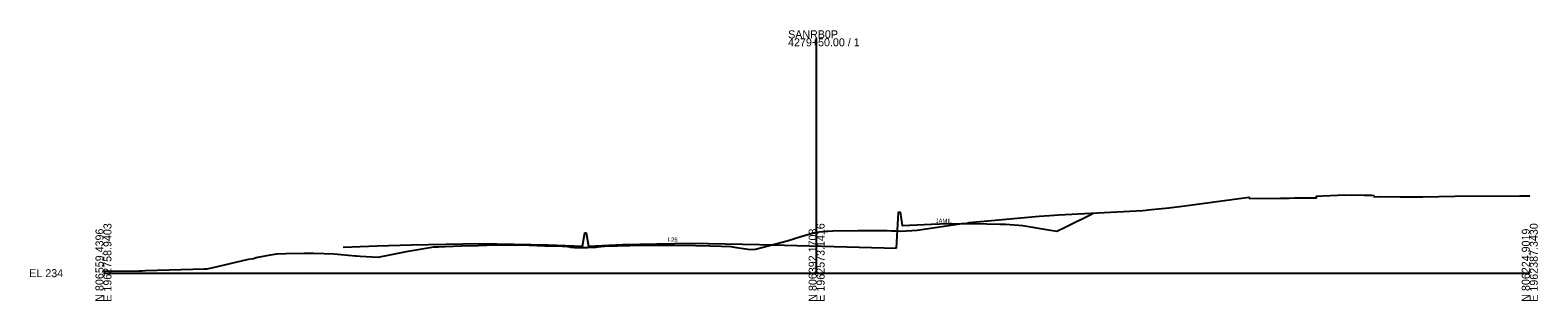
# Model space of a CAD drawing. Extents: x 1995641 to 1997170, y 790368 to 809963.
# Drawn here: x 1995641 to 1996170, y 790368 to 790463 of the extents above; entities that cross this region are included whole.
import ezdxf

# ---------------------------------------------------------------- set-up
doc = ezdxf.new("R2010")
doc.units = 0
for name, color, linetype in [('Default', 7, 'Continuous'), ('RD_GPK_XS_Cell', 7, 'Continuous'), ('RD_Sketch1', 7, 'Continuous'), ('RD_XS_ExGround', 7, 'Continuous'), ('RD_XS_Pave', 7, 'Continuous')]:
    doc.layers.add(name, color=color, linetype=linetype)

msp = doc.modelspace()

# ---------------------------------------------------------------- linework, layer by layer
at = {"layer": 'RD_GPK_XS_Cell'}
for p, q in [((1995917.06, 790378.11), (1995917.06, 790460.38)), ((1995667.06, 790378.11), (1995917.06, 790378.11)), ((1995917.06, 790378.11), (1996167.06, 790378.11))]:
    msp.add_line(p, q, dxfattribs=at)
at = {"layer": 'RD_XS_ExGround'}
msp.add_lwpolyline([(1995667.06, 790378.86), (1995679.41, 790378.96), (1995680.65, 790378.97), (1995681.75, 790378.99), (1995702.43, 790379.57), (1995703.46, 790379.59), (1995707.02, 790380.49), (1995717.86, 790383.07), (1995719.62, 790383.3), (1995720.62, 790383.6), (1995725.64, 790384.55), (1995726.98, 790384.72), (1995727.7, 790384.85), (1995730.97, 790384.97), (1995737.37, 790385.15), (1995740.79, 790385.08), (1995747.92, 790384.91), (1995755.32, 790384.22), (1995755.75, 790384.18), (1995757.05, 790384.1), (1995763.37, 790383.74), (1995773.85, 790385.79), (1995782.92, 790387.36), (1995784.57, 790387.37), (1995786.89, 790387.46), (1995792.6, 790387.65), (1995798.52, 790387.85), (1995804.53, 790388.04), (1995809.81, 790387.99), (1995816.24, 790387.91), (1995821.77, 790387.73), (1995827.93, 790387.53), (1995829.78, 790387.42), (1995830.55, 790387.38), (1995830.93, 790387.21), (1995832.23, 790387.14), (1995833.71, 790387.07), (1995835.48, 790387.11), (1995836.71, 790387.13), (1995839.33, 790387.21), (1995839.64, 790387.22), (1995839.88, 790387.29), (1995840.37, 790387.32), (1995840.65, 790387.41), (1995841.41, 790387.47), (1995842.75, 790387.55), (1995851.57, 790387.78), (1995855.14, 790387.89), (1995860.81, 790387.92), (1995867.27, 790387.97), (1995874.58, 790387.81), (1995879.66, 790387.7), (1995883.62, 790387.56), (1995886.95, 790387.45), (1995888.93, 790387.15), (1995893.84, 790386.36), (1995895.66, 790386.54), (1995906.75, 790389.49), (1995911.17, 790390.8), (1995916.78, 790392.42), (1995920.41, 790392.83), (1995921.02, 790392.87), (1995922.75, 790392.94), (1995931.49, 790393.07), (1995941.33, 790393.09), (1995941.82, 790393.05), (1995943.32, 790392.93), (1995944.87, 790392.89), (1995946.64, 790392.84), (1995952.35, 790393.16), (1995968.03, 790395.46), (1995969.76, 790395.68), (1995970.5, 790395.84), (1995977.07, 790396.43), (1995995.03, 790398.04), (1995998.71, 790398.33), (1996002.02, 790398.5), (1996026.9, 790399.83), (1996031.4, 790400.06), (1996034.44, 790400.36), (1996040.49, 790400.95), (1996042.39, 790401.2), (1996044.38, 790401.51), (1996068.67, 790404.72), (1996068.77, 790404.22), (1996079.65, 790404.38), (1996082.73, 790404.42), (1996084.52, 790404.45), (1996085.48, 790404.46), (1996092.26, 790404.55), (1996092.36, 790405.05), (1996094.56, 790405.17), (1996102.2, 790405.54), (1996109.08, 790405.49), (1996111.69, 790405.44), (1996112.42, 790405.37), (1996112.52, 790404.87), (1996114.32, 790404.91), (1996121.58, 790404.83), (1996126.45, 790404.81), (1996129.54, 790404.83), (1996140.78, 790405.06), (1996163.48, 790405.15), (1996167.06, 790405.22)], dxfattribs=at)
at = {"layer": 'RD_XS_Pave'}
for points in [[(1995945.04, 790386.9), (1995945.8, 790399.53), (1995946.3, 790399.53), (1995947.05, 790394.86), (1995949.62, 790394.97), (1995957.31, 790395.28), (1995960.2, 790395.34), (1995969.31, 790395.52), (1995972.22, 790395.46), (1995981.31, 790395.28), (1995982.82, 790395.25), (1995983.31, 790395.24), (1995984.78, 790395.13), (1995989.31, 790394.77), (1995998.36, 790393.26), (1996001.31, 790392.77), (1996004.25, 790394.24), (1996013.87, 790399.05)], [(1995751.04, 790387.21), (1995763.04, 790387.69), (1995775.04, 790387.99), (1995799.04, 790388.47), (1995823.04, 790387.99), (1995835.04, 790387.51), (1995835.79, 790392.29), (1995836.29, 790392.29), (1995837.04, 790387.62), (1995849.04, 790388.1), (1995873.04, 790388.58), (1995897.04, 790388.1), (1995945.04, 790386.9)]]:
    msp.add_lwpolyline(points, dxfattribs=at)

# ---------------------------------------------------------------- texts
at = {"layer": 'Default'}
msp.add_text('-', height=0.0001, dxfattribs=at).set_placement((1995667.06, 790378.11))
msp.add_text('-', height=0.0001, dxfattribs=at).set_placement((1995667.06, 790378.11))
at = {"layer": 'RD_GPK_XS_Cell'}
for s, p in [('SANRB0P', (1995907.06, 790460.38)), ('4279+50.00 / 1', (1995907.06, 790457.58)), ('EL 234', (1995641.06, 790376.71))]:
    msp.add_text(s, height=2.8, dxfattribs=at).set_placement(p)
for s, p in [('E 1962758.9403', (1995669.86, 790368.11)), ('E 1962573.1416', (1995919.86, 790368.11)), ('E 1962387.3430', (1996169.86, 790368.11)), ('N 806559.4396', (1995667.06, 790368.11)), ('N 806392.1708', (1995917.06, 790368.11)), ('N 806224.9019', (1996167.06, 790368.11))]:
    msp.add_text(s, height=2.8, rotation=90, dxfattribs=at).set_placement(p)
at = {"layer": 'RD_Sketch1'}
msp.add_text('248.34', height=0.1, dxfattribs=at).set_placement((1995916.85, 790392.35))
at = {"layer": 'RD_XS_Pave'}
for s, p in [('JAMIL', (1995958.77, 790395.68)), ('I-26', (1995864.78, 790389.11))]:
    msp.add_text(s, height=1.5, dxfattribs=at).set_placement(p)

doc.saveas('drawing.dxf')
